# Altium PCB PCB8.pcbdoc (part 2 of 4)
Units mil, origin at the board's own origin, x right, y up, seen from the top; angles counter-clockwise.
Board outline 6799.06 x 5716.8 mil, 2 copper layers (Top Layer, Bottom Layer); 312 components, 374 nets, 1333 pads, 994 vias.
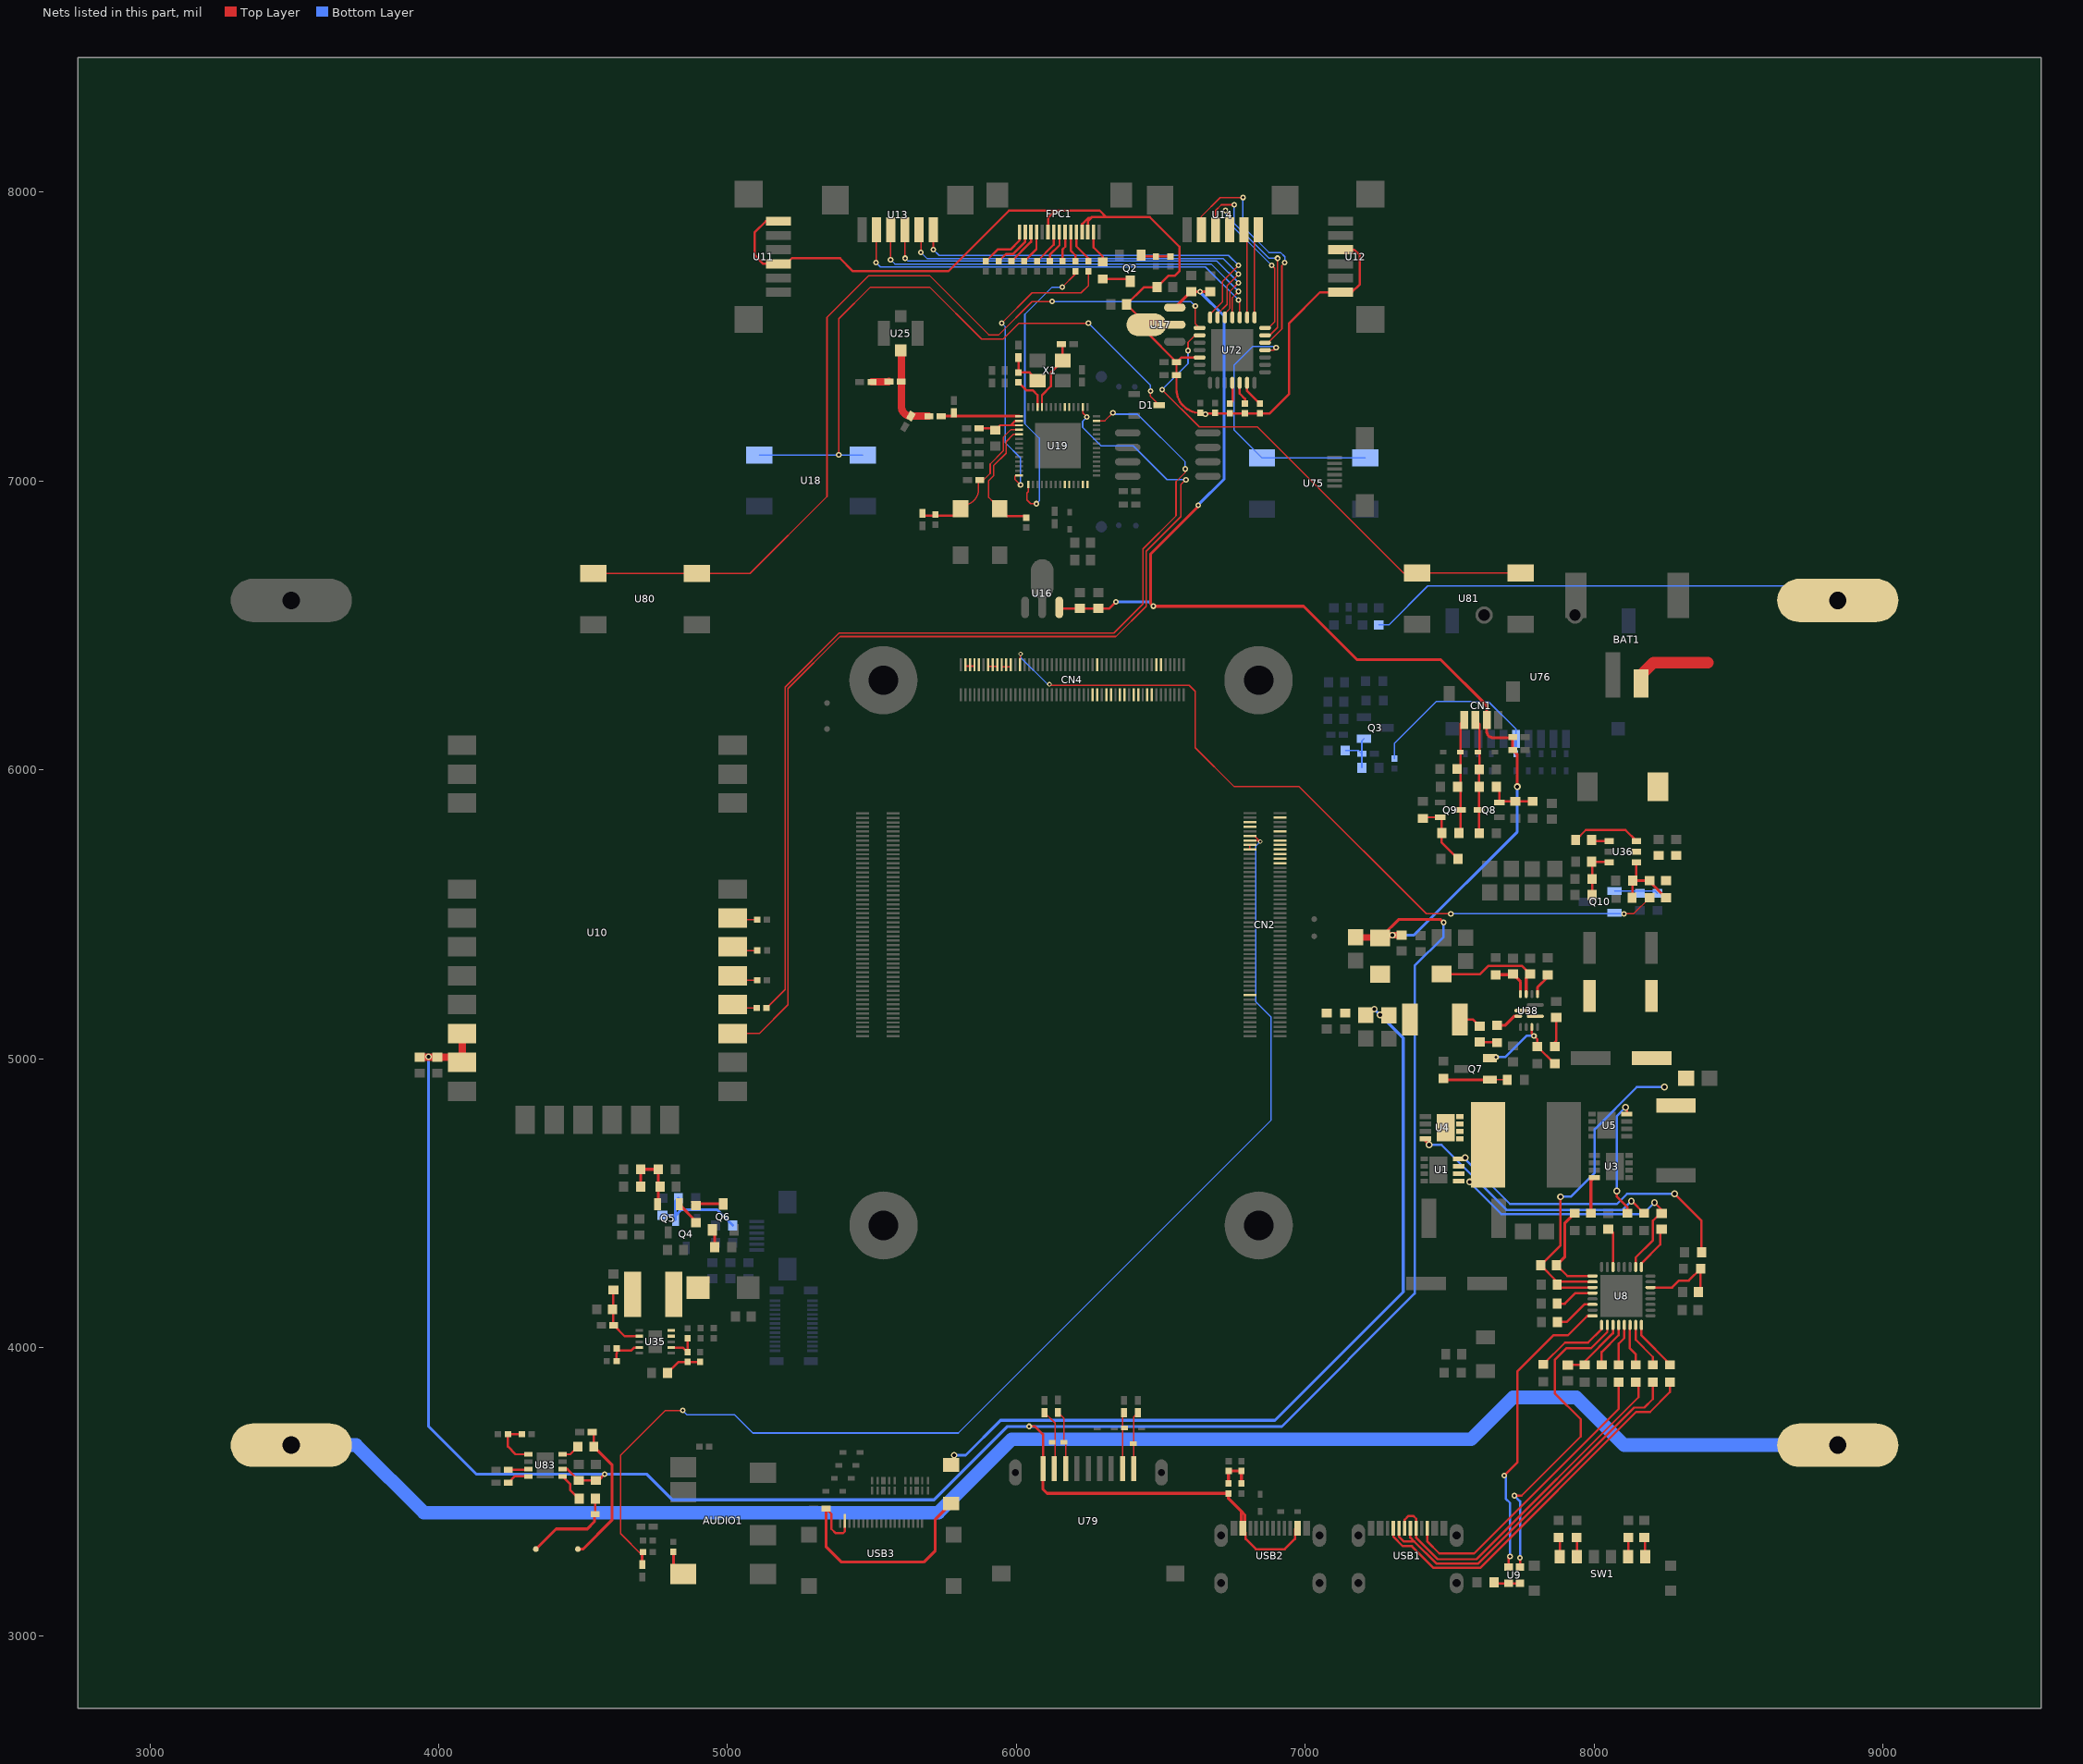
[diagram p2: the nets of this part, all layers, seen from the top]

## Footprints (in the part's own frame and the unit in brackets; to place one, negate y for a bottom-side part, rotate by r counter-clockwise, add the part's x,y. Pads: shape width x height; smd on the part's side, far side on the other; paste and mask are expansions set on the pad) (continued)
WIRELM-SMD_E32-400M30S [mm]
  rect 2.5x1.7 smd: 1(11.9,-16.469) 2(11.9,-13.929) 3(11.9,-11.389) 4(11.9,-3.819) 5(11.9,-1.279) 6(11.9,1.261) 7(11.9,3.801) 8(11.9,6.341) 9(11.9,8.881) 10(11.9,11.421) 11(11.9,13.961) 18(-11.9,13.961) 19(-11.9,11.421) 20(-11.9,8.881) 21(-11.9,6.341) 22(-11.9,3.801) 23(-11.9,1.261) 24(-11.9,-1.279) 25(-11.9,-3.819) 26(-11.9,-11.389) 27(-11.9,-13.929) 28(-11.9,-16.469)
  rect 1.7x2.5 smd: 12(6.35,16.469) 13(3.81,16.469) 14(1.27,16.469) 15(-1.27,16.469) 16(-3.81,16.469) 17(-6.35,16.469)
  silkscreen extent -12,-21.93 14.24,16.57
"垃圾桶LOGO COPY" [mil]
  silkscreen extent -95,-178 105,116

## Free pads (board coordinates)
  round 39.37 smd far side: 1(6294.47,6841.49) 1(6294.47,7361.49)
  round 236.22 hole 102.36: 201(6839.47,4422.4) 202(5540.26,4422.4) 203(5539.47,6310.19) 204(6838.68,6310.19)

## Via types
v1: diameter 19.7, hole 9.84, Top Layer to Bottom Layer, 526 vias
v2: diameter 15.75, hole 7.87, Top Layer to Bottom Layer, 322 vias
v3: diameter 19.68, hole 9.84, Top Layer to Bottom Layer, 98 vias
v4: diameter 23.62, hole 13.78, Top Layer to Bottom Layer, 39 vias
v5: diameter 24, hole 12, Top Layer to Bottom Layer, 9 vias

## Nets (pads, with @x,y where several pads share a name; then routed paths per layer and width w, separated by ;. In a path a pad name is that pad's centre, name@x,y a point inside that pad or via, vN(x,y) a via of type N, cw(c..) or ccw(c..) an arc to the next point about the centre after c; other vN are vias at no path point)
3V3: C21.2 C22.2 C395.2 C403.2 FPC1.3 FPC1.4 FPC1.10 R367.1 R368.1 R369.1 R370.2 R371.2 U11.1 U11.4 U12.1 U12.4 U17.2 U72.5 | length 4038.6
  Top Layer w7.87: U11.1@5175.65,7899.53 5132.5,7899.53 5094.47,7861.49 5094.47,7781.49 5124.07,7751.89 U11.4@5175.65,7751.89 5203.21,7751.89 5222.89,7771.57 5389.39,7771.57 5434.47,7726.49 5764.47,7726.49 5974.47,7936.49 6135.07,7936.49 ; 6110.07,7911.49 6135.07,7936.49 ; FPC1.4@6227.75,7861.85 6227.75,7889.77 6249.47,7911.49 6259.47,7911.49 ; FPC1.3@6247.44,7861.85 6247.44,7899.46 6259.47,7911.49 ; C395.2@6554.53,7366.46 C403.2@6554.53,7411.46 ; U72.5@6634.53,7427.63 6570.7,7427.63 C403.2@6554.53,7411.46 ; R370.2@6636.82,7235.67 6638.07,7234.42 R367.1@6739.94,7234.42 R369.1@6843.07,7234.42 6877.4,7234.42 6944.47,7301.49 6944.47,7546.49 7051.43,7653.46 U12.1@7123.29,7653.46 7161.43,7653.46 7189.47,7681.49 7189.47,7781.49 7169.86,7801.1 U12.4@7123.29,7801.1 ; 6135.07,7936.49 6288.81,7936.49 6311.78,7913.52 ; 6259.47,7911.49 6261.5,7913.52 6311.78,7913.52 ; 6311.78,7913.52 6462.44,7913.52 6564.47,7811.49 6564.47,7726.49 6549.47,7711.49 6526.91,7711.49 C21.2@6486.91,7671.49 6442.03,7671.49 C22.2@6382.03,7611.49 6450.27,7543.25 U17.2@6450.27,7541.49 6450.27,7515.72 C403.2@6554.53,7411.46
  Top Layer w7.9: C395.2@6554.53,7366.46 6554.53,7317.96 ccw(c6636.82,7317.96) R370.2@6636.82,7235.67
  Top Layer w8: FPC1.10@6109.64,7861.85 6109.64,7911.05 6110.07,7911.49
  other v3: 6654.47,7231.49
3V3_PWR_EN: CN4.74 Q10.2 R88.2 | length 2740.6
  Top Layer w5: CN4.74@6012.42,6357.67 6012.42,6389.44 6014.47,6391.49 v2(6014.47,6401.49) ; v2(6114.47,6296.49) 6118.69,6292.27 6598.69,6292.27 6619.47,6271.49 6619.47,6076.49 6754.47,5941.49 6979.47,5941.49 7419.47,5501.49 v1(7504.47,5501.49) ; v1(8104.47,5501.49) 8137.53,5501.49 R88.2@8193.3,5557.26
  Bottom Layer w5: v2(6014.47,6401.49) 6014.47,6389.65 6107.62,6296.49 v2(6114.47,6296.49) ; v1(7504.47,5501.49) v1(8104.47,5501.49)
5V_PWR_EN: CN4.14
$1N1265: C40.2 L3.1 U19.2 U19.3 | length 187
  Top Layer w7.87: C40.2@5870.73,7182.34 L3.1@5933.16,7182.34 ; L3.1@5927.18,7176.36 L3.1@5933.16,7182.34 ; U19.3@6009.66,7193.01 5980.99,7193.01 ; U19.2@6009.66,7208.76 5996.74,7208.76 5980.99,7193.01 ; L3.1@5933.16,7182.34 5943.83,7193.01 5980.99,7193.01
$1N1275: R41.2 U19.54 | length 125.6
  Top Layer w7.87: R41.2@6007.18,7341.77 6034.71,7314.24 6056.72,7314.24 6072.95,7298.01 U19.54@6072.95,7256.3
$1N1307: C37.2 R41.1 X1.1 | length 129.6
  Top Layer w7.87: C37.2@6007.18,7427.35 R41.1@6007.18,7375.85 6045.66,7375.85 X1.1@6073.71,7347.8
$1N1308: C30.1 U19.53 X1.3 | length 249.1
  Top Layer w7.87: U19.53@6088.7,7256.3 6088.7,7297.56 6119.47,7328.33 6119.47,7375.84 X1.3@6160.33,7416.7 6160.33,7469.2 C30.1@6155.72,7473.81
$1N1320: C45.2 L4.2 U19.1 | length 260.2
  Top Layer w10: L4.2@5749.47,7224.51 U19.1@6009.66,7224.51
$1N1322: C47.2 L4.1 L5.1 U25.1 | length 310.4
  Top Layer w25.59: U25.1@5604.47,7452.44 ccw(c5604.47,7449.45) 5601.47,7449.45 L5.1@5601.47,7344.66 5601.47,7258.8 ccw(c5635.2,7258.8) C47.2@5635.2,7225.08 5635.61,7224.67 L4.1@5697.1,7224.67
$1N1382: boot.1 R388.1 U19.5 | length 434.9
  Top Layer w5: boot.1@5942.18,6903.93 5936.66,6903.93 5921.37,6919.22 5921.37,6926.3 5904.47,6943.2 5904.47,7001.49 5921.37,7018.39 5921.37,7053.39 5964.47,7096.49 5964.47,7136.49 5989.5,7161.52 U19.5@6009.66,7161.52
  Top Layer w7.87: boot.1@5942.18,6903.93 5968.16,6877.95 R388.1@6034.47,6877.95
$1N1392: U19.24
$1N3038: FPC1.5 R45.1 | length 118.4
  Top Layer w7.87: FPC1.5@6208.07,7861.85 6208.07,7812.9 6249.23,7771.73 R45.1@6249.23,7760.54
$1N3048: FPC1.6 R42.1 | length 108.1
  Top Layer w7.87: FPC1.6@6188.38,7861.85 6189.47,7860.75 6189.47,7796.49 6204.85,7781.11 R42.1@6204.85,7760.54
$1N3058: FPC1.7 R39.1 | length 105.3
  Top Layer w7.87: R39.1@6160.48,7760.54 6160.48,7802.5 6169.47,7811.49 6169.47,7861.07 FPC1.7@6168.7,7861.85
$1N3068: FPC1.8 R37.1 | length 115.3
  Top Layer w7.87: R37.1@6116.1,7760.54 6116.1,7783.13 6149.47,7816.49 6149.47,7861.38 FPC1.8@6149.01,7861.85
$1N3078: FPC1.9 R36.1 | length 125.2
  Top Layer w7.87: R36.1@6071.73,7760.54 6129.33,7818.14 FPC1.9@6129.33,7861.85
$1N3208: FPC1.15 R30.1 | length 175.7
  Top Layer w7.87: R30.1@5894.23,7760.54 5935.18,7801.49 5979.47,7801.49 6011.22,7833.24 FPC1.15@6011.22,7861.85
$1N3221: FPC1.14 R31.1 | length 154.1
  Top Layer w7.87: R31.1@5938.6,7760.54 5964.56,7786.49 5989.47,7786.49 6030.91,7827.93 FPC1.14@6030.91,7861.85
$1N3231: FPC1.13 R33.1 | length 129.3
  Top Layer w7.87: R33.1@5982.98,7760.54 6050.59,7828.15 FPC1.13@6050.59,7861.85
$1N3252: FPC1.12 R35.1 | length 119.1
  Top Layer w7.87: R35.1@6027.35,7760.54 6069.47,7802.65 6069.47,7861.05 FPC1.12@6070.27,7861.85
$1N3432: Q2.1 R47.1 R48.2 | length 103.4
  Top Layer w7.87: Q2.1@6431.87,7781.77 6436.04,7777.6 R48.2@6483.52,7777.6 R47.1@6533.52,7777.6
$1N3517: Q2.3 R46.2 | length 98.9
  Top Layer w7.87: R46.2@6299.23,7699.55 6386.41,7699.55 6394.47,7691.49 Q2.3@6394.47,7691.22
$1N3518: FPC1.2 R46.1 | length 116.3
  Top Layer w7.87: FPC1.2@6267.12,7861.85 6267.12,7808.85 6299.23,7776.73 R46.1@6299.23,7758.87
$1N4606: U19.23
$1N7321: R24.1 U10.22 | length 93.2
  Top Layer w5: U10.22@5017.97,5286.84 ccw(c5033.32,5286.84) 5033.32,5271.49 R24.1@5102.43,5271.49
$1N7323: R26.1 U10.23 | length 92.1
  Top Layer w5: U10.23@5017.97,5386.84 ccw(c5030.33,5386.84) 5030.33,5374.48 R26.1@5103.01,5374.48
$1N7325: R27.1 U10.24 | length 87.5
  Top Layer w5: U10.24@5017.97,5486.84 ccw(c5023.32,5486.84) 5023.32,5481.49 R27.1@5102.43,5481.49
$1N7464: R23.1 U10.21 | length 89.7
  Top Layer w5: U10.21@5017.97,5186.84 ccw(c5029.36,5186.84) 5029.36,5175.45 R23.1@5101.17,5175.45
$1N7607: U19.47
$1N7610: U19.48
$1N9541: R10.2 U5.4 | length 420.2
  Top Layer w7.87: v4(8079.47,4541.49) 8079.47,4521.49 8116.35,4484.61 R10.2@8116.35,4464.53 ; v4(8109.47,4831.49) 8113.81,4827.15 U5.4@8113.81,4807.79
  Bottom Layer w7.87: v4(8079.47,4541.49) 8079.47,4801.49 v4(8109.47,4831.49)
$1N9548: R9.2 U4.4 | length 892.9
  Top Layer w7.87: U4.4@7416.01,4722.26 7416.01,4714.95 v4(7429.47,4701.49) ; v4(8129.47,4506.49) 8131.06,4506.49 R9.2@8173.02,4464.53
  Bottom Layer w7.87: v4(7429.47,4701.49) 7471.85,4701.49 7696.85,4476.49 8099.47,4476.49 v4(8129.47,4506.49)
$1N9582: R7.2 U3.4 | length 128.1
  Top Layer w10: R7.2@7989.68,4464.53 7989.68,4575.95 U3.4@8001.47,4587.73
$1N9598: R20.2 U8.31 | length 162.7
  Top Layer w7.87: U8.31@8144.7,4077.69 8144.7,4026.27 8204.02,3966.94 R20.2@8204.02,3939.53
$1N9599: R21.2 U8.32 | length 179
  Top Layer w7.87: U8.32@8164.4,4077.69 8164.4,4041.57 8263.02,3942.94 R21.2@8263.02,3939.53
$1N9600: R19.2 U8.30 | length 146.9
  Top Layer w7.87: U8.30@8125,4077.69 8124.47,4077.17 8124.47,3996.49 8145.02,3975.94 R19.2@8145.02,3939.53
$1N9601: R18.2 U8.29 | length 146.1
  Top Layer w7.87: R18.2@8086.02,3939.53 8086.02,4013.04 8105.3,4032.32 U8.29@8105.3,4077.69
$1N9602: U8.26 U9.3 | length 1118.1
  Top Layer w7.87: v1(7724.47,3486.49) 7749.47,3486.49 7954.47,3691.49 7954.47,3751.49 7864.47,3841.49 7864.47,3956.49 7904.47,3996.49 7989.47,3996.49 8046.3,4053.32 U8.26@8046.3,4077.69 ; U9.3@7744.15,3240.04 v1(7744.15,3271.49)
  Bottom Layer w7.87: v1(7724.47,3486.49) 7744.15,3466.81 v1(7744.15,3271.49)
$1N9603: R17.2 U8.25 | length 266.9
  Top Layer w7.87: R17.2@7824.47,3941.15 7899.81,4016.49 7979.47,4016.49 8026.6,4063.62 U8.25@8026.6,4077.69
$1N9608: C12.1 R22.2 U8.27 | length 237.5
  Top Layer w7.87: C12.1@7909.47,3939.05 7967.54,3939.05 R22.2@7968.02,3939.53 7968.02,3950.67 8066,4048.65 U8.27@8066,4077.69
$1N9610: R14.2 U9.1 U9.4 | length 91.5
  Top Layer w8: R14.2@7654.13,3186.49 7657.67,3182.95 U9.1@7704.78,3182.95 U9.4@7744.15,3182.95
$1N9622: R15.2 U8.28 | length 162.5
  Top Layer w7.87: R15.2@8027.02,3939.53 8027.02,3984.04 8085.7,4042.72 U8.28@8085.7,4077.69
$1N9623: C9.2 U8.20 | length 138
  Top Layer w7.87: C9.2@7872.47,4152.26 7873.24,4151.49 7899.47,4151.49 7935.87,4187.89 U8.20@7995.1,4187.89
$1N9626: C11.2 U8.22 | length 147
  Top Layer w7.87: C11.2@7873.28,4087.77 7905.74,4087.77 7966.57,4148.59 U8.22@7995.1,4148.59
$1N9627: U8.24 U9.2 | length 1045.8
  Top Layer w7.87: v1(7689.47,3556.49) 7734.47,3601.49 7734.47,3916.49 7859.47,4041.49 7909.47,4041.49 7977.17,4109.19 U8.24@7995.1,4109.19 ; U9.2@7704.78,3240.04 7704.78,3271.81 v1(7709.47,3276.49)
  Bottom Layer w7.87: v1(7689.47,3556.49) 7694.47,3551.49 7694.47,3476.49 7709.47,3461.49 v1(7709.47,3276.49)
$1N9630: C4.2 L1.1 U1.1 U1.2 U1.3 U4.5 U4.6 U4.7 U4.8 U8.10 | length 973.4
  Top Layer w7.87: U8.10@8144.7,4278.49 8144.7,4311.72 8204.47,4371.49 8204.47,4439.05 C4.2@8229.47,4464.05 ; v4(8209.47,4501.49) 8234.47,4476.49 C4.2@8234.47,4464.05
  Bottom Layer w7.87: v4@7567.52,4573.44 7679.47,4461.49 8169.47,4461.49 v4(8209.47,4501.49)
  other v4: 7569.65,4572.93
$1N9636: R12.1 SW1.2 | length 66.9
  Top Layer w7.87: R12.1@7939.47,3341.83 7940.89,3340.41 SW1.2@7940.89,3275.55
$1N9637: R11.2 SW1.1 | length 68.3
  Top Layer w7.87: R11.2@7876.97,3341.83 7881.83,3336.97 SW1.1@7881.83,3275.55
$1N9644: R2.1 U1.4 | length 1072.9
  Top Layer w7.87: v4(8279.47,4531.49) 8372.34,4438.62 R2.1@8372.34,4329.53
  Top Layer w10: U1.4@7532.04,4653.15 7535.38,4656.49 v4(7554.47,4656.49)
  Bottom Layer w7.87: v4(7554.47,4656.49) 7554.47,4651.49 7709.47,4496.49 8079.47,4496.49 8114.47,4531.49 v4(8279.47,4531.49)
$1N9649: R13.1 SW1.5 | length 66.9
  Top Layer w7.87: SW1.5@8118.05,3275.55 8119.47,3276.97 R13.1@8119.47,3341.83
$1N9650: R16.1 SW1.6 | length 67.4
  Top Layer w7.87: R16.1@8174.47,3341.83 8177.11,3339.19 SW1.6@8177.11,3275.55
$1N12616: D1.3 U18.1 U18.2 | length 2222.2
  Top Layer w5: v3(5385.1,7090.07) 5385.1,7562.13 5494.47,7671.49 5699.47,7671.49 5879.47,7491.49 5954.47,7491.49 6009.47,7546.49 v3(6249.47,7546.49) ; v3(6464.47,7311.49) 6464.47,7293.13 D1.3@6494.47,7263.13
  Bottom Layer w5: U18.2@5110.34,7090.07 v3(5385.1,7090.07) U18.1@5468.6,7090.08 ; v3(6249.47,7546.49) 6464.47,7331.49 v3(6464.47,7311.49)
$1N14613: C48.2 L5.2 | length 59.1
  Top Layer w25.59: C48.2@5500.01,7343.21 5557.09,7343.21 L5.2@5558.56,7344.66
$1N28296: R367.2 U72.11 | length 76.1
  Top Layer w7.87: R367.2@6739.94,7268.5 6749.47,7278.02 6749.47,7338.28 U72.11@6747.82,7339.93
$1N28297: R368.2 U72.12 | length 79.4
  Top Layer w7.87: U72.12@6773.41,7339.93 6773.41,7302.55 6791.51,7284.46 R368.2@6791.51,7268.05
$1N28298: R369.2 U72.13 | length 90
  Top Layer w7.87: U72.13@6799,7339.93 6799,7311.96 6842.46,7268.5 R369.2@6843.07,7268.5
$1N42754: C413.2 U83.3 | length 70.4
  Top Layer w7.87: C413.2@4240.93,3576.49 4308.2,3576.49 U83.3@4310.41,3578.7
$1N42758: C414.2 U83.4 | length 78.4
  Top Layer w7.87: C414.2@4240.93,3531.49 4262.54,3553.1 U83.4@4310.41,3553.1
$1N42976: L14.1 U83.5 | length 102.4
  Top Layer w7.87: U83.5@4428.52,3553.1 4454.47,3527.16 4454.47,3506.49 4484.81,3476.15 L14.1@4486.91,3476.15
$1N42978: L13.1 U83.8 | length 64.4
  Top Layer w7.87: U83.8@4428.52,3629.88 4455.3,3629.88 L13.1@4481.91,3656.49
$1N43424: -.1 C417.1 L13.2 | length 492.5
  Top Layer w7.87: C417.1@4530.93,3706.49 4537.02,3700.4 L13.2@4537.02,3656.49
  Top Layer w10: -.1@4481.78,3301.41 4499.39,3301.41 4599.47,3401.49 4599.47,3594.05 L13.2@4537.02,3656.49
$1N43427: +.1 C418.1 L14.2 | length 323.4
  Top Layer w7.87: C418.1@4542.07,3422.78 L14.2@4542.07,3476.1
  Top Layer w10: +.1@4336.15,3301.41 4406.23,3371.49 4514.47,3371.49 4539.47,3396.49 4539.47,3420.18 C418.1@4542.07,3422.78
$1N43466: R383.2 R384.1 U83.1 | length 174
  Top Layer w7.87: R383.2@4287.43,3701.49 4285.35,3699.41 R384.1@4239.32,3699.41 4239.32,3656.49 4265.93,3629.88 U83.1@4310.41,3629.88
$1N56076: U19.27
$1N56079: U19.28
$3N5478: CN4.94 CN4.96 CN4.98 | length 41.9
  Top Layer w5: CN4.98@5826.18,6359.06 5856.42,6359.06 5856.42,6349.78 CN4.94@5854.74,6348.1
$3N5591: CN4.92
$3N6200: D20.2 R59.2 U76.5 | length 658.1
  Bottom Layer w5: R59.2@7309.47,6038.53 7309.47,6091.49 7454.47,6236.49 7634.47,6236.49 7729.82,6141.14 U76.5@7729.82,6106.77
  Bottom Layer w10: D20.2@7729.47,6056.02 7729.47,6106.41 U76.5@7729.82,6106.77
$3N7118: C57.1 Q3.1 R61.1 R63.2 | length 165.8
  Bottom Layer w5: R63.2@7139.13,6066.49 7185.16,6066.49 C57.1@7196.39,6055.26 ; R61.1@7196.59,6006.99 7196.39,6007.19 C57.1@7196.39,6055.26 ; Q3.1@7203.48,6107.86 7196.39,6100.77 C57.1@7196.39,6055.26
$3N8858: AUDIO1.2 R50.1 | length 91.2
  Top Layer w10: R50.1@4812.43,3292.41 4812.43,3249.65 AUDIO1.2@4846.67,3215.41
$3N10139: R49.2 R51.1 R53.2 R55.2 | length 132.2
  Top Layer w10: R51.1@6734.47,3528.53 6734.47,3571.63 R55.2@6735.17,3572.34 R49.2@6779.47,3572.34 R53.2@6779.47,3528.53
$3N10242: C49.2 D10.2 U79.8 | length 194.9
  Top Layer w5: U79.8@6367.58,3581.1 6367.58,3768.79 C49.2@6372.65,3773.86
$3N10292: C50.2 D11.2 U79.9 | length 198.3
  Top Layer w5: U79.9@6406.95,3581.1 6406.95,3760.45 C50.2@6420.36,3773.86
$3N10376: D6.2 L6.2 U79.2 | length 208.7
  Top Layer w5: L6.2@6098.07,3773.87 6133.99,3737.94 6133.99,3583.73 U79.2@6131.36,3581.1
$3N10406: D7.2 L7.2 U79.3 | length 204.8
  Top Layer w5: L7.2@6144.47,3775.04 6164.94,3754.56 D7.2@6164.94,3671.49 6170.73,3665.71 U79.3@6170.73,3581.1
$3N11399: C71.2 C412.2 L8.2 L9.1 U35.7 | length 227.3
  Top Layer w7.87: C71.2@4604.47,4198.93 4604.47,4077.95 C412.2@4605.93,4076.49 4643.62,4038.8 U35.7@4694.53,4038.8
$3N11421: D26.2 L9.2 U35.4 U35.5
$3N11460: R381.1 R382.1 U35.9 | length 130.5
  Top Layer w7.87: R381.1@4615.68,3952.01 4615.68,3978.31 4616.51,3979.14 R382.1@4616.51,3996.49 4624.24,3988.76 4665.87,3988.76 4676.53,3999.43 U35.9@4694.53,3999.43
$3N11471: R376.2 R380.2 U35.2 | length 110.9
  Top Layer w7.87: U35.2@4805.67,3999.43 4845.53,3999.43 R376.2@4861.43,3983.53 4861.57,3983.67 R380.2@4861.57,4032.01
$3N11495: C73.2 R376.1 R377.2 | length 128.2
  Top Layer w7.87: C73.2@4792.03,3911.49 4829.99,3949.45 R376.1@4861.43,3949.45 R377.2@4904.47,3949.45
$3N12532: Q6.3 R72.1 | length 97.3
  Top Layer w10: R72.1@4890.01,4491.46 4895.62,4497.08 Q6.3@4985.01,4497.08
$3N12560: Q6.1 R73.2 | length 62.9
  Top Layer w10: Q6.1@4947.61,4406.52 4955.35,4398.78 R73.2@4955.35,4346.8
$3N12564: C61.1 Q5.2 R69.2 R70.1 R71.1 | length 243.2
  Top Layer w10: R69.2@4699.67,4556.8 R70.1@4699.67,4616.8 R71.1@4760.35,4616.8 4760.35,4498.17 Q5.2@4757.61,4495.43
$3N12575: Q5.1 R72.2 | length 87.1
  Top Layer w10: Q5.1@4832.41,4495.43 4890.01,4437.83 R72.2@4890.01,4432.14
$3N12811: Q4.1 R64.1 R65.1 R66.2 | length 359.5
  Bottom Layer w10: R66.2@4774.47,4456.83 4804.7,4456.83 Q4.1@4819.8,4441.73 Q4.1@4819.8,4456.83 ; R64.1@4829.81,4516.49 4819.8,4506.49 Q4.1@4819.8,4456.83 ; R65.1@5018.25,4422.31 4964.06,4476.49 4839.47,4476.49 Q4.1@4819.8,4456.83
$3N24551: C89.1 L11.1 U38.7 | length 77.7
  Top Layer w8: L11.1@7536.04,5135.04 7581.99,5135.04 C89.1@7604.43,5112.6
$3N24554: C89.2 R92.2 | length 60.9
  Top Layer w7.87: C89.2@7604.43,5057.48 7662.33,5057.48 R92.2@7664.43,5055.38
$3N24558: R92.1 U38.8 | length 86.7
  Top Layer w10: R92.1@7664.43,5114.7 7691.94,5114.7 7723.78,5146.55 U38.8@7737.92,5146.55
$3N24693: R93.2 U38.3 | length 81.2
  Top Layer w10: U38.3@7804.85,5223.33 7804.85,5246.88 7839.77,5281.8 R93.2@7839.77,5290.04
$3N24908: C99.2 R101.2 U38.6 | length 140.9
  Top Layer w10: R101.2@7659.43,5290.38 7717.33,5290.38 C99.2@7719.43,5292.48 7745.79,5266.12 U38.6@7745.79,5223.33
$3N25599: C85.2 R87.1 R88.1 R91.2 U36.4 | length 270.9
  Top Layer w7.87: C85.2@8132.03,5556.49 8134.13,5558.59 R91.2@8134.13,5616.49 8146.71,5629.08 U36.4@8146.71,5679.09
  Top Layer w10: R91.2@8134.13,5616.49 8193.21,5616.49 R88.1@8193.3,5616.58 8193.3,5613.01 R87.1@8249.47,5556.83
$3N25630: C76.2 U36.1 | length 61.3
  Top Layer w7.87: C76.2@7992.03,5756.49 7994.63,5753.89 U36.1@8052.22,5753.89
$3N25641: C76.1 U36.6 U37.1 | length 239.9
  Top Layer w7.87: C76.1@7936.91,5756.49 7971.91,5791.49 8109.11,5791.49 U36.6@8146.71,5753.89
$3N25659: C77.2 R86.1 R89.2 U36.3 | length 177.1
  Top Layer w7.87: R89.2@7994.13,5566.49 R86.1@7994.13,5621.49 7994.13,5679.39 C77.2@7992.03,5681.49 8049.82,5681.49 U36.3@8052.22,5679.09
$3N26750: C60.2 U30.2 USB3.18 | length 903.9
  Top Layer w7.87: C60.2@5340.93,3441.49 5359.47,3422.95 5359.47,3371.49 5374.47,3356.49 5399.47,3356.49 5406.32,3363.34 USB3.18@5406.32,3399.09
  Top Layer w10: C60.2@5340.93,3441.49 5340.93,3310.03 5394.47,3256.49 5679.47,3256.49 5719.47,3296.49 5719.47,3404.56 U30.2@5774.47,3459.56
$3N29756: Q7.1 R85.2 R385.2 | length 222.6
  Top Layer w5: Q7.1@7639.84,4926.95 7699.35,4926.95 R385.2@7699.81,4926.49
  Top Layer w10: R85.2@7479.47,4931.83 7484.35,4926.95 Q7.1@7639.84,4926.95
$3N29784: Q7.2 R84.2 R90.1 U38.11 | length 322.4
  Top Layer w8: U38.11@7785.16,5109.16 7784.47,5108.46 7784.47,5086.49 v1(7792.43,5078.53) 7803.92,5067.04 R84.2@7803.92,5041.9 7863.24,4982.58 R90.1@7864.47,4982.58
  Bottom Layer w8: v1(7661.26,5004.85) 7692.83,5004.85 7766.51,5078.53 v1(7792.43,5078.53)
$3N30068: Q9.2 R103.1 R106.1 R107.2 | length 231
  Top Layer w7.87: R103.1@7407.76,5831.54 7411.83,5835.61 Q9.2@7467.41,5835.61 7473.1,5829.92 R107.2@7473.1,5781.2 7473.1,5747.52 R106.1@7529.13,5691.49
$3N30821: Q8.2 R94.1 R97.1 R99.2 | length 175.2
  Top Layer w7.87: R99.2@7662.42,5941.2 7673.11,5930.51 Q8.2@7673.11,5886.79 7677.18,5890.86 R94.1@7727.76,5890.86 R97.1@7787.76,5890.86
$3N31158: CN1.4 D28.1 Q9.3 R104.2 R105.2 R107.1 | length 414.9
  Top Layer w7.87: R105.2@7526.56,6003.39 R105.2@7538.11,5991.85 ; R107.1@7532.42,5781.2 7538.11,5786.89 Q9.3@7538.11,5861.2 R105.2@7538.11,5991.85 ; CN1.4@7550.41,6172.28 7538.11,6159.98 R105.2@7538.11,5991.85
$3N31177: CN1.3 D27.1 Q8.3 R95.2 R96.2 R99.1 | length 397.4
  Top Layer w7.87: CN1.3@7589.78,6172.28 7603.1,6158.97 R96.2@7603.1,6001.2 7602.41,6000.51 Q8.3@7602.41,5861.2 7602.41,5781.21 R95.2@7602.76,5780.86
$3N38895: U77.2 U78.1 | length 5608.4
  Bottom Layer w47.24: U78.1@3566.97,3661.49 3714.47,3661.49 3948.93,3427.03 5730,3427.03 5984.47,3681.49 7574.47,3681.49 7719.47,3826.49 7939.47,3826.49 8104.47,3661.49 U77.2@8844.47,3661.49
$3N65029: Q10.1 R386.2 R387.2 | length 152.4
  Bottom Layer w5: Q10.1@8070.62,5580.08 8212.05,5580.08 R387.2@8219.79,5572.34
+1V8: C51.2 CN2.88 CN2.90 R57.2 | length 4282.3
  Top Layer w5: 4704.47,3280.32 4629.47,3355.32 4629.47,3626.49 4784.47,3781.49 v1(4844.47,3781.49) ; CN2.88@6808.76,5755.47 v2@6840.49,5755.47 ; CN2.90@6815.27,5771.43 6824.53,5771.43 v2@6840.49,5755.47 ; v2(6844.47,5751.49) v2@6840.49,5755.47
  Top Layer w10: C51.2@4704.47,3247.95 4704.47,3280.32 4704.47,3288.53 R57.2@4707.43,3291.49
  Bottom Layer w5: v1(4844.47,3781.49) 4859.47,3766.49 5024.47,3766.49 5087.47,3703.49 5799.2,3703.49 6882.48,4786.78 6882.48,5143.48 6829.47,5196.49 6829.47,5736.49 v2(6844.47,5751.49)
+3.3V: CN2.84 CN2.86 | length 15.7
  Top Layer w5: CN2.84@6808.76,5723.97 CN2.86@6808.76,5739.72
+5V: C19.2 C20.2 C23.2 C24.2 C90.1 C96.1 C397.2 C407.1 C415.2 C416.2 C419.2 C420.2 CN1.2 CN2.77 CN2.79 CN2.81 CN2.83 CN2.85 CN2.87 L12.2 R51.2 U10.9 U10.10 U16.3 U17.3 U79.1 U83.6 USB2.A4 USB2.A9 USB2.B4 USB2.B9 | length 12818.9
  Top Layer w5: L12.2@7259.43,5417.74 7292.42,5417.74 v4(7302.28,5427.6)
  Top Layer w7.87: U83.6@4428.52,3578.7 4445.35,3578.7 C415.2@4484.47,3539.59 C416.2@4544,3539.59 ; v3(6044.47,3726.49) 6064.47,3726.49 6091.99,3698.97 U79.1@6091.99,3581.1 ; U16.3@6148.57,6562.29 6151.93,6558.93 C20.2@6219.47,6558.93 C23.2@6284.47,6558.93 6321.91,6558.93 v1(6344.47,6581.49) ; C19.2@6671.76,7655.09 C19.2@6676.76,7655.09
  Top Layer w8: USB2.A4@6778.88,3373.98 6794.47,3358.38 6794.47,3336.49 6829.47,3301.49 6929.47,3301.49 6964.47,3336.49 6964.47,3370.59 USB2.B4@6967.85,3373.97
  Top Layer w10: C416.2@4544,3539.59 4552.56,3539.59 v3(4574.47,3561.49) ; U79.1@6091.99,3581.1 6091.99,3508.97 6106.51,3494.45 R51.2@6734.47,3494.45 6734.47,3476.49 6778.88,3432.09 ; U17.3@6548.67,7600.59 6603.16,7655.09 v1(6635.75,7655.09) C19.2@6671.76,7655.09 ; v1(6629.47,6916.49) 6629.47,6911.49 6464.47,6746.49 6464.47,6576.49 v1(6474.47,6566.49) 6994.47,6566.49 7179.47,6381.49 7469.47,6381.49 7629.14,6221.82 CN1.2@7629.14,6172.28 7629.14,6131.82 ccw(c7649.47,6131.82) 7649.47,6111.49 7716.59,6111.49 ccw(c7716.59,6113.7) C96.1@7718.8,6113.7 C90.1@7718.8,6068.7 7734.47,6053.03 v4(7734.47,5941.49) ; USB2.A4@6778.88,3373.98 6778.88,3432.09 ; USB2.B9@6790.69,3373.98 6790.69,3420.28 6778.88,3432.09 ; USB2.B4@6967.85,3373.97 USB2.A9@6979.67,3373.97 ; L12.2@7269.29,5427.6 7323.18,5481.49 7469.47,5481.49 v1(7479.47,5471.49)
  Top Layer w23.62: C407.1@7174.43,5419.41 7261.1,5419.41 7269.29,5427.6 v4(7302.28,5427.6) C397.2@7334.43,5427.6
  Top Layer w25.59: C419.2@3934.73,5004.66 C420.2@3995.54,5004.66 4063.15,5004.66 U10.10@4080.96,4986.84 U10.9@4080.96,5086.84
  Bottom Layer w7.87: 6919.47,3726.49 7379.47,4186.49 7379.47,5321.49 7479.47,5421.49 v1(7479.47,5471.49)
  Bottom Layer w10: v4(3964.47,5006.49) 3964.47,3726.49 4129.47,3561.49 v3(4574.47,3561.49) 4719.47,3561.49 4808.83,3472.13 5715.11,3472.13 5969.47,3726.49 v3(6044.47,3726.49) 6919.47,3726.49 ; v1(6344.47,6581.49) 6459.47,6581.49 v1(6474.47,6566.49) ; v1(6629.47,6916.49) 6719.47,7006.49 6719.47,7571.37 v1(6635.75,7655.09) ; v4(7302.28,5427.6) 7376.43,5427.6 7734.47,5785.65 v4(7734.47,5941.49)
+5V_INPUT: C92.2 C93.2 C97.1 C404.2 C405.2 L10.1 L11.2 L12.1 U30.1 U38.5 | length 3253.1
  Top Layer w8: L10.1@7472.83,5292.92 7605.9,5292.92 7634.47,5321.49 7750.43,5321.49 C97.1@7779.43,5292.48
  Top Layer w10: U30.1@5774.47,3593.42 5784.47,3603.42 v4(5784.47,3626.49) ; U38.5@7765.48,5223.33 7765.48,5278.54 C97.1@7779.43,5292.48
  Bottom Layer w10: v4(5784.47,3626.49) 5824.47,3626.49 5945.31,3747.33 6895.31,3747.33 7339.47,4191.49 7339.47,5071.49 v4(7260.07,5150.89) v4(7239.47,5171.49)
A0: U13.4 U72.25 | length 1453.5
  Top Layer w5: v3(5564.47,7766.49) 5564.47,7869.92 U13.4@5564.86,7870.31 ; U72.25@6747.82,7566.51 6747.82,7634.84 v3(6769.47,7656.49)
  Bottom Layer w5: v3(5564.47,7766.49) 5579.47,7751.49 6674.47,7751.49 v3(6769.47,7656.49)
A1: U13.5 U72.24 | length 1484.8
  Top Layer w5: v3(5514.47,7756.49) 5514.47,7869.13 U13.5@5515.65,7870.31 ; v3(6769.47,7626.49) 6773.41,7622.55 U72.24@6773.41,7566.51
  Bottom Layer w5: v3(5514.47,7756.49) 5529.47,7741.49 6654.47,7741.49 v3(6769.47,7626.49)
A2: U14.4 U72.20 | length 698.6
  Top Layer w5: U14.4@6689.86,7870.31 6689.86,7936.89 6709.47,7956.49 v3(6754.47,7956.49) ; U72.20@6861.11,7504.4 6877.38,7504.4 6904.47,7531.49 v3(6904.47,7771.49)
  Bottom Layer w5: v3(6754.47,7956.49) 6754.47,7891.49 6874.47,7771.49 v3(6904.47,7771.49)
A3: U14.5 U72.19 | length 837.4
  Top Layer w5: U14.5@6640.65,7870.31 6640.65,7916.12 6706.03,7981.49 v3(6784.47,7981.49) ; U72.19@6861.11,7478.81 6871.79,7478.81 6919.47,7526.49 6919.47,7746.49 v3(6929.47,7756.49)
  Bottom Layer w5: v3(6784.47,7981.49) 6784.47,7881.49 6874.47,7791.49 6914.47,7791.49 6929.47,7776.49 v3(6929.47,7756.49)
A4: U72.18 U75.1 U75.2 | length 935.2
  Top Layer w5: U72.18@6861.11,7453.22 6891.2,7453.22 v3(6899.47,7461.49)
  Bottom Layer w5: v3(6899.47,7461.49) 6894.47,7466.49 6819.47,7466.49 6754.47,7401.49 6754.47,7175.94 U75.2@6850.34,7080.07 U75.1@7208.6,7080.08
A5: U72.1 U80.1 U80.2 | length 3096
  Top Layer w5: U80.1@4535.34,6680.08 U80.2@4893.6,6680.07 ; U80.2@4893.6,6680.07 5078.04,6680.07 5344.47,6946.49 5344.47,7566.49 5489.47,7711.49 5699.47,7711.49 5904.47,7506.49 5939.47,7506.49 6054.47,7621.49 v3(6124.47,7621.49) ; v3(6619.47,7606.49) 6619.47,7545.05 U72.1@6634.53,7529.99
  Bottom Layer w5: v3(6124.47,7621.49) 6604.47,7621.49 v3(6619.47,7606.49)
A6: U72.2 U81.1 U81.2 | length 1755.7
  Top Layer w5: v3(6504.47,7316.49) 6633.57,7187.39 6834.52,7187.39 7340.24,6681.67 U81.1@7387.88,6681.67 U81.2@7746.14,6681.66 ; v3(6594.47,7451.49) 6594.47,7480.27 6618.6,7504.4 U72.2@6634.53,7504.4
  Bottom Layer w5: v3(6504.47,7316.49) 6594.47,7406.49 v3(6594.47,7451.49)
AIN0: CN2.96
AIN1: CN2.94
B0: U13.1 U72.28 | length 1369.3
  Top Layer w5: v3@5712.5,7801.49 U13.1@5712.5,7870.31 ; U72.28@6671.05,7566.51 6671.05,7578.07 6714.47,7621.49 6714.47,7691.49 v3(6769.47,7746.49)
  Bottom Layer w5: v3(5712.55,7801.49) 5732.55,7781.49 6734.47,7781.49 v3(6769.47,7746.49)
B1: U13.2 U72.27 | length 1392.6
  Top Layer w5: U13.2@5663.29,7870.31 5669.47,7864.14 v3(5669.47,7791.49) ; U72.27@6696.64,7566.51 6696.64,7578.66 6729.47,7611.49 6729.47,7676.49 v3(6769.47,7716.49)
  Bottom Layer w5: v3(5669.47,7791.49) 5690.47,7770.49 6715.47,7770.49 v3(6769.47,7716.49)
B2: U13.3 U72.26 | length 1428.7
  Top Layer w5: U13.3@5614.08,7870.31 5614.47,7869.93 v3(5614.47,7771.49) ; U72.26@6722.23,7566.51 6722.23,7580.11 6738.82,7596.7 6738.82,7655.84 v3(6769.47,7686.49)
  Bottom Layer w5: v3(5614.47,7771.49) 5624.47,7761.49 6694.47,7761.49 v3(6769.47,7686.49)
B3: U14.1 U72.22 | length 309.2
  Top Layer w5: U72.22@6824.59,7566.51 6824.59,7857.4 U14.1@6837.5,7870.31
B4: U14.2 U72.23 | length 308.2
  Top Layer w5: U14.2@6788.29,7870.31 6799,7859.61 U72.23@6799,7566.51
B5: U14.3 U72.21 | length 569.9
  Top Layer w5: v3(6724.47,7936.49) 6739.08,7921.88 U14.3@6739.08,7870.31 ; U72.21@6861.11,7529.99 6872.97,7529.99 6894.47,7551.49 6894.47,7736.49 v3(6884.47,7746.49)
  Bottom Layer w5: v3(6724.47,7936.49) 6724.47,7906.49 v3(6884.47,7746.49)
BAT: BAT1.1 C1.2 C6.1 C7.2 C74.2 C75.2 C86.1 C87.1 C88.2 R87.2 R90.2 R98.2 R375.2 U6.1 U8.18 U8.19 U36.5 U38.1 U77.1 | length 3233.5
  Top Layer w7.87: C6.1@7815.46,4284.87 7872.47,4227.86 C7.2@7872.47,4217 ; U8.19@7995.1,4207.59 7881.88,4207.59 C7.2@7872.47,4217 ; U8.18@7995.1,4227.29 7882.76,4227.29 C7.2@7872.47,4217
  Top Layer w8: C6.1@7815.46,4284.87 7884.47,4353.89 v4(7884.47,4521.49) ; R90.2@7864.47,5041.9 7864.47,5056.9 7869.43,5061.86 C88.2@7869.43,5142.48
  Top Layer w39.37: BAT1.1@8163.68,6328.7 8206.48,6371.49 8394.47,6371.49
  Bottom Layer w5: R98.2@7254.47,6501.83 7289.81,6501.83 7424.47,6636.49 8794.47,6636.49 U77.1@8844.47,6586.49
  Bottom Layer w8: v4(7884.47,4521.49) 7919.47,4521.49 8002.66,4604.68 8002.66,4755.53 8148.62,4901.49 v4(8244.47,4901.49)
BAT_3V7_LOSE: CN4.78 CN4.80 CN4.82 | length 37
  Top Layer w5: CN4.82@5951.47,6357.3 CN4.78@5979.46,6357.3 ; CN4.78@5978.92,6356.75 CN4.78@5979.46,6357.3 ; CN4.78@5979.23,6349.19 5979.46,6349.42 CN4.78@5979.46,6357.3
BAT_3V7_PLUS: CN4.84 CN4.86 CN4.88 | length 29.8
  Top Layer w5: CN4.88@5905.71,6357.69 5929.87,6357.69 5930.06,6357.49 5935.17,6357.49 CN4.84@5935.37,6357.69
BST1: C4.1 U8.9 | length 157.4
  Top Layer w7.87: U8.9@8164.4,4278.49 8164.4,4291.42 8229.47,4356.49 C4.1@8229.47,4408.93
BST2: C5.1 U8.14 | length 135.2
  Top Layer w7.87: C5.1@8054.47,4408.93 8066,4397.41 U8.14@8066,4278.49
BT_NDIS: CN2.91
CAM_GPIO: CN2.97
CAM_PWR_2: CN4.12
CAM_RESET_1: CN4.40
CC1: R21.1 USB1.A5 | length 1319.2
  Top Layer w7.87: USB1.A5@7305.26,3373.98 7305.26,3344.45 7338.22,3311.49 7369.47,3311.49 7444.47,3236.49 7605.68,3236.49 8145.68,3776.49 8194.47,3776.49 8263.02,3845.04 R21.1@8263.02,3880.21
CC2: R18.1 USB1.B5 | length 1026.3
  Top Layer w7.87: USB1.B5@7423.37,3373.98 7423.37,3327.59 7464.47,3286.49 7584.97,3286.49 8086.02,3787.54 R18.1@8086.02,3880.21
CHIP_PU: boot1.1 C44.2 C402.1 R40.1 U19.4 | length 518.9
  Top Layer w5: boot1.1@5814.85,6916.45 ccw(c5814.85,6970.34) 5868.75,6970.34 5868.75,6994.18 cw(c5879.11,6994.18) C402.1@5875.27,7003.81 ; C402.1@5873.64,7003.81 C402.1@5875.27,7003.81 ; U19.4@6009.66,7177.27 5980.25,7177.27 5954.47,7151.49 5954.47,7103.76 5909.47,7058.76 5909.47,7026.49 5886.78,7003.81 C402.1@5875.27,7003.81
  Top Layer w7.87: C44.2@5674.03,6879.44 5782.7,6879.44 boot1.1@5807.18,6903.93
CS: R23.2 U19.41 | length 3437.2
  Top Layer w5: R23.2@5135.25,5175.45 5199.47,5239.67 5199.47,6286.49 5386.16,6473.18 6337.58,6473.18 6438.53,6574.14 6438.53,6765.01 6552.94,6879.41 6552.94,6997.89 6584.7,7029.65 v3(6584.7,7041.81) ; U19.41@6277.97,7208.76 6306.74,7208.76 v3(6334.47,7236.49)
  Bottom Layer w5: v3(6334.47,7236.49) 6339.47,7231.49 6419.47,7231.49 6584.7,7066.26 v3(6584.7,7041.81)
CS1: R42.2 U19.15 | length 1017.5
  Top Layer w5: U19.15@6041.46,6987.99 6041.46,6963.48 6036.46,6958.48 6036.46,6934.5 6049.47,6921.49 v3(6069.47,6921.49) ; v3(6159.47,7671.49) 6204.85,7716.88 R42.2@6204.85,7726.46
  Bottom Layer w5: v3(6069.47,6921.49) 6079.47,6931.49 6079.47,7148.2 6029.5,7198.17 6029.5,7577.46 6123.53,7671.49 v3(6159.47,7671.49)
CSN1: C8.2 R5.1 U8.6 | length 283.3
  Top Layer w7.87: U8.6@8195.9,4207.59 8270.57,4207.59 8294.47,4231.49 8328.47,4231.49 R5.1@8369.05,4272.06 8369.05,4198.51 C8.2@8362.03,4191.49
CSN2: C6.2 R8.1 U8.17 | length 345.7
  Top Layer w7.87: C6.2@7870.58,4284.87 7908.46,4246.99 U8.17@7995.1,4246.99
  Top Layer w10: C6.2@7870.58,4284.87 7899.47,4313.77 7899.47,4430.99 R8.1@7933.02,4464.53
DC1: R45.2 U19.14 | length 1045.3
  Top Layer w5: v3(5949.47,7546.49) 6054.47,7651.49 6224.23,7651.49 6249.23,7676.49 R45.2@6249.23,7726.46 ; U19.14@6009.66,7019.79 5997.77,7019.79 5994.47,7016.49 5994.47,7006.49 v3(6014.47,6986.49)
  Bottom Layer w5: v3(5949.47,7546.49) 5961.86,7534.1 5961.86,7132.55 6014.47,7079.95 v3(6014.47,6986.49)
DIO0: U10.20 U19.44 | length 3691.5
  Top Layer w5: U10.20@5017.97,5086.84 5109.82,5086.84 5209.47,5186.49 5209.47,6281.49 5389.47,6461.49 6344.47,6461.49 6449.47,6566.49 6449.47,6756.49 6569.47,6876.49 6569.47,6987.97 6582.19,7000.7 v3@6582.94,6999.95 ; U19.44@6230.43,7256.3 6230.43,7235.53 v3(6244.47,7221.49)
  Bottom Layer w5: v3(6244.47,7221.49) 6229.47,7206.49 6229.47,7185.55 6293.53,7121.49 6404.47,7121.49 6521.42,7004.55 v3(6587.21,7004.55)
DM: R20.1 USB1.A7 USB1.B7 | length 1294
  Top Layer w7.87: USB1.B7@7324.94,3373.98 7324.94,3344.45 7341.52,3327.87 7378.09,3327.87 ; USB1.A7@7364.31,3373.98 7364.31,3341.65 7378.09,3327.87 ; R20.1@8204.02,3880.21 8204.02,3821.04 8174.47,3791.49 8139.47,3791.49 7599.47,3251.49 7454.47,3251.49 7378.09,3327.87
DP: R19.1 USB1.A6 USB1.B6 | length 1234.2
  Top Layer w7.87: USB1.A6@7344.63,3373.98 7344.63,3403.5 7357.62,3416.49 7374.47,3416.49 7384.47,3406.49 7384.47,3374.45 USB1.B6@7384,3373.98 7384,3341.96 7459.47,3266.49 7593.26,3266.49 8154.47,3827.71 8154.47,3870.76 R19.1@8145.02,3880.21
EDP_TX_AUXN: CN4.41
EDP_TX_AUXP: CN4.39
EDP_TX_D0N: CN4.17
EDP_TX_D0P: CN4.15
EDP_TX_D1N: CN4.23
EDP_TX_D1P: CN4.21
EDP_TX_D2N: CN4.29
EDP_TX_D2P: CN4.27
EDP_TX_D3N: CN4.35
EDP_TX_D3P: CN4.33
EEPROM_NWP: CN2.20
